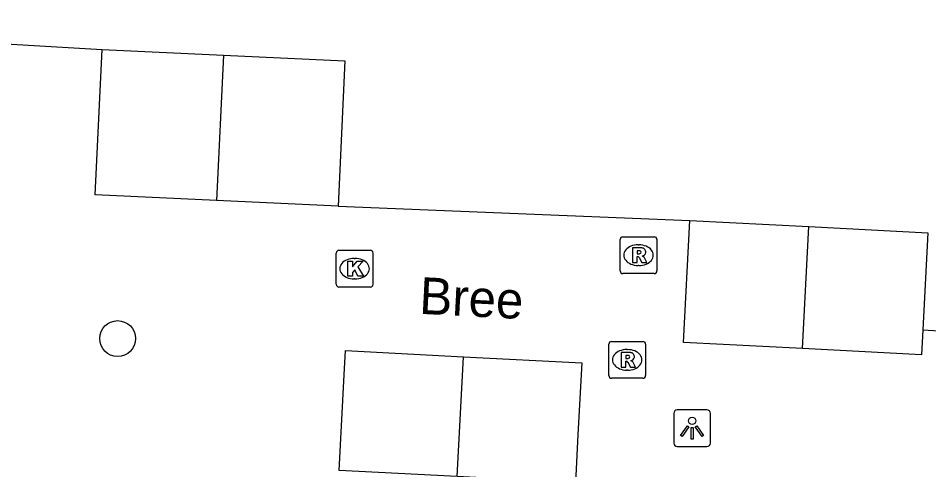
# Model space of a CAD drawing. Extents: x 162990 to 165007, y 383433 to 384336.
# Drawn here: x 164474.99 to 164499.76, y 383661.98 to 383674.27 of the extents above; entities that cross this region are included whole.
import ezdxf

# ---------------------------------------------------------------- set-up
doc = ezdxf.new("R2010")
doc.units = 0
for name, color, linetype in [('IMGEO_Boom', 7, 'Continuous'), ('IMGEO_Kolk', 7, 'Continuous'), ('IMGEO_Lichtpunt', 7, 'Continuous'), ('IMGEO_Openbare_ruimte_label', 7, 'Continuous'), ('IMGEO_Pand', 7, 'Continuous'), ('IMGEO_Rioolput', 7, 'Continuous'), ('IMGEO_Voetpad_open', 7, 'Continuous')]:
    doc.layers.add(name, color=color, linetype=linetype)

msp = doc.modelspace()

# ---------------------------------------------------------------- linework, layer by layer
at = {"layer": 'IMGEO_Boom'}
msp.add_circle((164477.697, 383665.548), 0.489, dxfattribs=at)
at = {"layer": 'IMGEO_Kolk'}
for p, q in [((164483.642, 383667.025), (164483.642, 383667.877)), ((164483.717, 383667.951), (164484.569, 383667.951)), ((164484.643, 383667.877), (164484.643, 383667.025)), ((164484.13, 383667.731), (164484.155, 383667.731)), ((164484.153, 383667.171), (164484.128, 383667.171)), ((164484.569, 383666.951), (164483.717, 383666.951))]:
    msp.add_line(p, q, dxfattribs=at)
for points in [[(164483.642, 383667.025), (164483.642, 383667.877)], [(164483.717, 383667.951), (164484.569, 383667.951)], [(164484.643, 383667.877), (164484.643, 383667.025)], [(164483.963, 383667.651), (164484.086, 383667.651), (164484.086, 383667.5), (164484.216, 383667.651), (164484.38, 383667.651), (164484.234, 383667.5), (164484.387, 383667.251), (164484.235, 383667.251), (164484.15, 383667.415), (164484.086, 383667.348), (164484.086, 383667.251), (164483.963, 383667.251), (164483.963, 383667.651)], [(164484.569, 383666.951), (164483.717, 383666.951)]]:
    msp.add_lwpolyline(points, dxfattribs=at)
for centre, start, end in [((164483.719, 383667.875), 91.552, 178.448), ((164483.719, 383667.875), 91.552, 178.448), ((164484.567, 383667.875), 1.552, 88.448), ((164484.567, 383667.875), 1.552, 88.448), ((164483.719, 383667.027), 181.552, 268.448), ((164483.719, 383667.027), 181.552, 268.448), ((164484.567, 383667.027), 271.552, 358.448), ((164484.567, 383667.027), 271.552, 358.448)]:
    msp.add_arc(centre, 0.0765, start, end, dxfattribs=at)
for centre, major_axis, ratio, start_param, end_param in [((164484.129, 383667.451), (-0.387, 0.002), 0.722429, 4.712389, 7.853982), ((164484.154, 383667.451), (-0.39, 0.002), 0.717154, 1.570796, 4.712389)]:
    msp.add_ellipse(centre, major_axis=major_axis, ratio=ratio, start_param=start_param, end_param=end_param, dxfattribs=at)
at = {"layer": 'IMGEO_Lichtpunt'}
for p, q in [((164493.728, 383663.609), (164492.92, 383663.609)), ((164493.728, 383663.609), (164492.92, 383663.609)), ((164492.826, 383663.514), (164492.826, 383662.707)), ((164492.826, 383663.514), (164492.826, 383662.707)), ((164493.822, 383662.707), (164493.822, 383663.514)), ((164493.822, 383662.707), (164493.822, 383663.514)), ((164492.92, 383662.613), (164493.728, 383662.613)), ((164492.92, 383662.613), (164493.728, 383662.613))]:
    msp.add_line(p, q, dxfattribs=at)
for points in [[(164493.2, 383663.178), (164493.239, 383663.15), (164493.051, 383662.888), (164493.013, 383662.915), (164493.2, 383663.178)], [(164493.302, 383663.13), (164493.349, 383663.13), (164493.349, 383662.808), (164493.302, 383662.808), (164493.302, 383663.13)], [(164493.412, 383663.15), (164493.45, 383663.177), (164493.637, 383662.915), (164493.598, 383662.887), (164493.412, 383663.15)]]:
    msp.add_lwpolyline(points, dxfattribs=at)
msp.add_circle((164493.325, 383663.312), 0.0994, dxfattribs=at)
for centre, start, end in [((164492.92, 383663.514), 90, 180), ((164492.92, 383663.514), 90, 180), ((164493.728, 383663.514), 0, 90), ((164493.728, 383663.514), 0, 90), ((164492.92, 383662.707), 180, 270), ((164492.92, 383662.707), 180, 270), ((164493.728, 383662.707), 270, 0), ((164493.728, 383662.707), 270, 360)]:
    msp.add_arc(centre, 0.0946, start, end, dxfattribs=at)
at = {"layer": 'IMGEO_Pand'}
for points in [[(164480.39, 383669.304), (164477.087, 383669.459), (164477.272, 383673.411)], [(164477.272, 383673.411), (164480.575, 383673.257)], [(164480.575, 383673.257), (164480.39, 383669.304)], [(164480.575, 383673.257), (164483.879, 383673.102), (164483.694, 383669.149)], [(164483.694, 383669.149), (164480.39, 383669.304)], [(164496.325, 383665.275), (164493.087, 383665.444), (164493.26, 383668.763)], [(164493.26, 383668.763), (164496.498, 383668.594)], [(164496.325, 383665.275), (164496.498, 383668.594)], [(164496.498, 383668.594), (164499.737, 383668.425), (164499.599, 383665.791)], [(164499.599, 383665.791), (164499.563, 383665.106), (164496.325, 383665.275)], [(164486.935, 383661.792), (164483.722, 383661.96), (164483.858, 383664.563), (164483.892, 383665.222), (164487.105, 383665.054)], [(164486.935, 383661.792), (164487.105, 383665.054)], [(164487.105, 383665.054), (164490.322, 383664.886), (164490.22, 383662.936), (164490.151, 383661.624), (164486.935, 383661.792)]]:
    msp.add_lwpolyline(points, dxfattribs=at)
at = {"layer": 'IMGEO_Rioolput'}
for p, q in [((164491.367, 383667.392), (164491.367, 383668.244)), ((164491.442, 383668.318), (164492.294, 383668.318)), ((164492.368, 383668.244), (164492.368, 383667.392)), ((164491.855, 383668.098), (164491.88, 383668.098)), ((164491.878, 383667.538), (164491.853, 383667.538)), ((164492.294, 383667.318), (164491.442, 383667.318)), ((164491.058, 383664.544), (164491.058, 383665.396)), ((164491.133, 383665.47), (164491.985, 383665.47)), ((164492.059, 383665.396), (164492.059, 383664.544)), ((164491.546, 383665.25), (164491.571, 383665.25)), ((164491.569, 383664.69), (164491.544, 383664.69)), ((164491.985, 383664.47), (164491.133, 383664.47))]:
    msp.add_line(p, q, dxfattribs=at)
for points in [[(164491.367, 383667.392), (164491.367, 383668.244)], [(164491.442, 383668.318), (164492.294, 383668.318)], [(164492.368, 383668.244), (164492.368, 383667.392)], [(164491.956, 383668.016), (164491.704, 383668.018), (164491.704, 383667.618)], [(164491.704, 383667.618), (164491.828, 383667.618), (164491.828, 383667.78), (164491.839, 383667.78)], [(164491.882, 383667.937), (164491.828, 383667.937), (164491.828, 383667.856)], [(164491.828, 383667.856), (164491.88, 383667.856)], [(164491.886, 383667.751), (164491.957, 383667.618), (164492.097, 383667.618), (164492.032, 383667.744)], [(164492.294, 383667.318), (164491.442, 383667.318)], [(164491.058, 383664.544), (164491.058, 383665.396)], [(164491.133, 383665.47), (164491.985, 383665.47)], [(164492.059, 383665.396), (164492.059, 383664.544)], [(164491.647, 383665.168), (164491.395, 383665.17), (164491.395, 383664.77)], [(164491.573, 383665.089), (164491.519, 383665.089), (164491.519, 383665.008)], [(164491.395, 383664.77), (164491.519, 383664.77), (164491.519, 383664.932), (164491.53, 383664.932)], [(164491.519, 383665.008), (164491.571, 383665.008)], [(164491.577, 383664.903), (164491.648, 383664.77), (164491.788, 383664.77), (164491.723, 383664.896)], [(164491.985, 383664.47), (164491.133, 383664.47)]]:
    msp.add_lwpolyline(points, dxfattribs=at)
for centre, radius, start, end in [((164491.444, 383668.242), 0.0765, 91.552, 178.448), ((164491.444, 383668.242), 0.0765, 91.552, 178.448), ((164492.292, 383668.242), 0.0765, 1.552, 88.448), ((164492.292, 383668.242), 0.0765, 1.552, 88.448), ((164491.955, 383667.906), 0.109, 350.3612, 89.416), ((164491.838, 383667.727), 0.0533, 26.0293, 88.6989), ((164491.864, 383668.045), 0.19, 274.7715, 282.9687), ((164491.888, 383667.841), 0.0964, 77.0061, 93.1865), ((164491.902, 383667.898), 0.0378, 276.6634, 79.6772), ((164491.953, 383667.906), 0.112, 277.5842, 350.9817), ((164491.937, 383667.691), 0.108, 29.5134, 73.7905), ((164491.444, 383667.394), 0.0765, 181.552, 268.448), ((164491.444, 383667.394), 0.0765, 181.552, 268.448), ((164492.292, 383667.394), 0.0765, 271.552, 358.448), ((164492.292, 383667.394), 0.0765, 271.552, 358.448), ((164491.135, 383665.394), 0.0765, 91.552, 178.448), ((164491.135, 383665.394), 0.0765, 91.552, 178.448), ((164491.983, 383665.394), 0.0765, 1.552, 88.448), ((164491.983, 383665.394), 0.0765, 1.552, 88.448), ((164491.579, 383664.993), 0.0964, 77.0061, 93.1865), ((164491.593, 383665.05), 0.0378, 276.6634, 79.6772), ((164491.646, 383665.058), 0.109, 350.3612, 89.416), ((164491.644, 383665.058), 0.112, 277.5842, 350.9817), ((164491.529, 383664.879), 0.0533, 26.0293, 88.6989), ((164491.555, 383665.197), 0.19, 274.7715, 282.9687), ((164491.628, 383664.843), 0.108, 29.5134, 73.7905), ((164491.135, 383664.546), 0.0765, 181.552, 268.448), ((164491.135, 383664.546), 0.0765, 181.552, 268.448), ((164491.983, 383664.546), 0.0765, 271.552, 358.448), ((164491.983, 383664.546), 0.0765, 271.552, 358.448)]:
    msp.add_arc(centre, radius, start, end, dxfattribs=at)
for centre, major_axis, ratio, start_param, end_param in [((164491.854, 383667.818), (-0.387, 0.002), 0.722429, 4.712389, 7.853982), ((164491.879, 383667.818), (-0.39, 0.002), 0.717154, 1.570796, 4.712389), ((164491.545, 383664.97), (-0.387, 0.002), 0.722429, 4.712389, 7.853982), ((164491.57, 383664.97), (-0.39, 0.002), 0.717154, 1.570796, 4.712389)]:
    msp.add_ellipse(centre, major_axis=major_axis, ratio=ratio, start_param=start_param, end_param=end_param, dxfattribs=at)
at = {"layer": 'IMGEO_Voetpad_open'}
for points in [[(164462.753, 383674.265), (164477.272, 383673.411)], [(164483.694, 383669.149), (164493.26, 383668.763)], [(164499.599, 383665.791), (164531.557, 383663.848)]]:
    msp.add_lwpolyline(points, dxfattribs=at)

# ---------------------------------------------------------------- texts
at = {"layer": 'IMGEO_Openbare_ruimte_label'}
msp.add_text('Bree', height=1, rotation=357.0775, dxfattribs=at).set_placement((164485.889, 383666.224))

doc.saveas('drawing.dxf')
